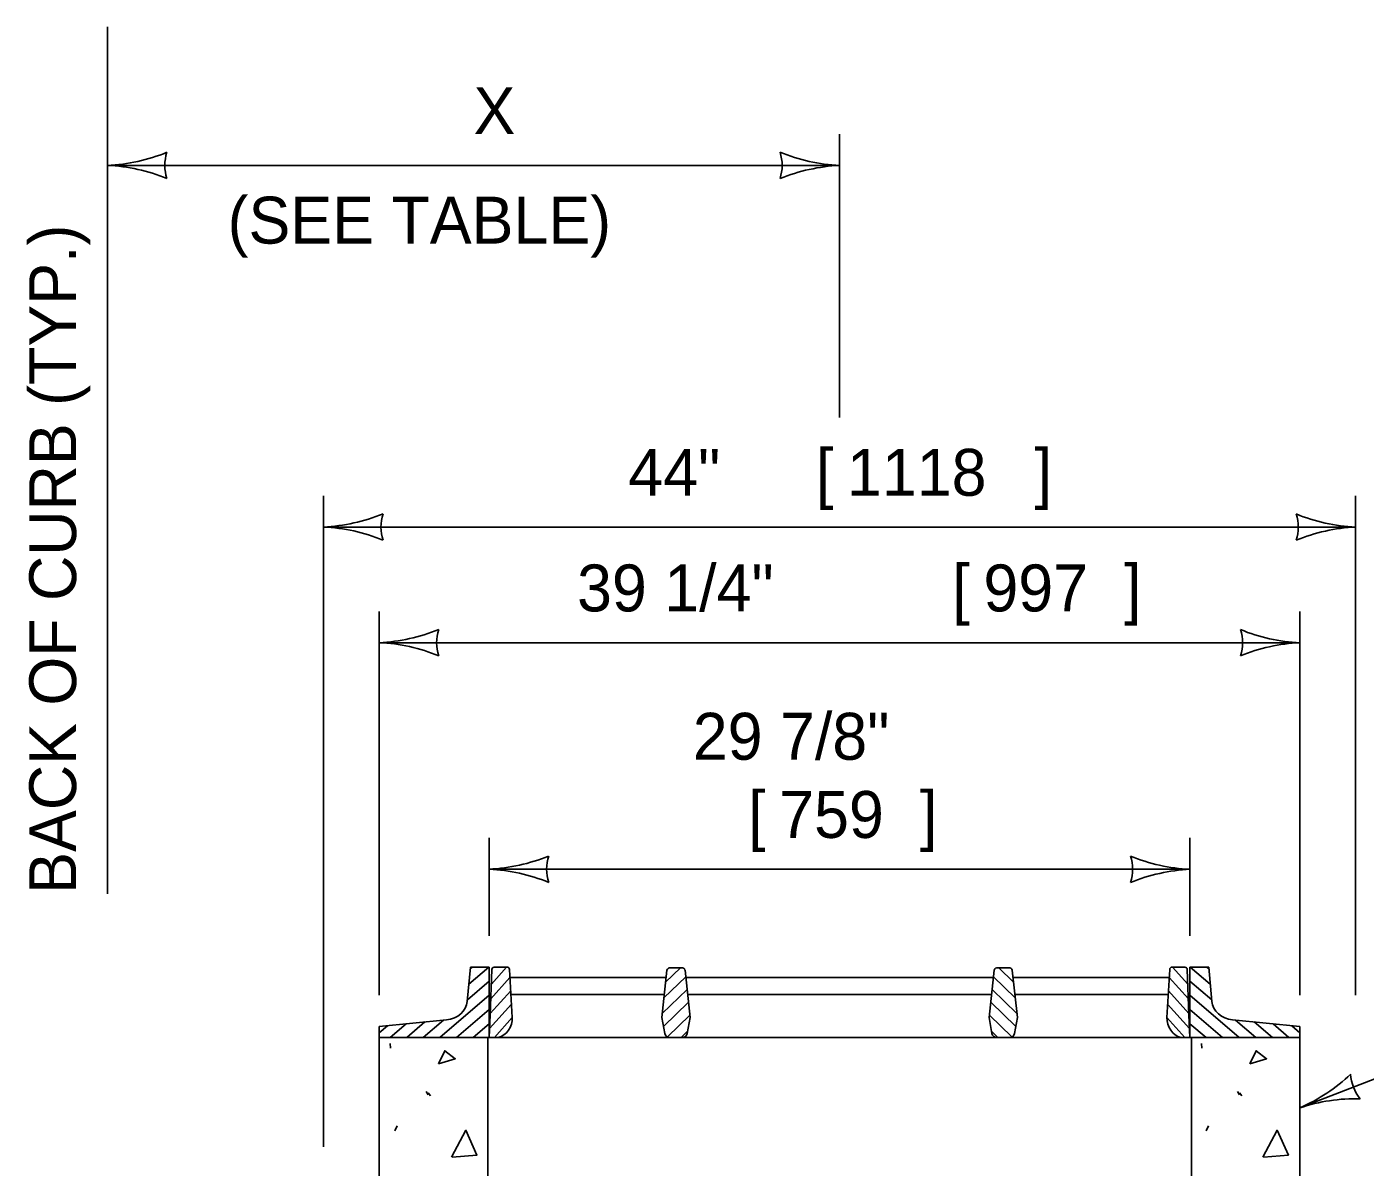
# Model space of a CAD drawing. Extents: x 49991.4 to 50041.6, y 49987.6 to 50011.4.
# Drawn here: x 50037.958 to 50039.67, y 49993.451 to 49994.909 of the extents above; entities that cross this region are included whole.
import ezdxf

# ---------------------------------------------------------------- set-up
doc = ezdxf.new("R2010")
doc.units = 0
for name, color, linetype in [('Level 1', 7, 'Continuous'), ('Level 2', 7, 'Continuous'), ('Level 3', 7, 'Continuous')]:
    doc.layers.add(name, color=color, linetype=linetype)

msp = doc.modelspace()

# ---------------------------------------------------------------- linework, layer by layer
at = {"layer": 'Level 1'}
for p, q in [((50038.5258, 49993.7068), (50038.5217, 49993.6628)), ((50038.5237, 49993.6848), (50038.5493, 49993.7068)), ((50038.5256, 49993.7046), (50038.5281, 49993.7068)), ((50038.5497, 49993.7068), (50038.5258, 49993.7068)), ((50038.5497, 49993.6168), (50038.5497, 49993.7068)), ((50038.5531, 49993.7036), (50038.5511, 49993.6456)), ((50038.5525, 49993.6851), (50038.5719, 49993.7068)), ((50038.5727, 49993.7068), (50038.5561, 49993.7068)), ((50038.5793, 49993.6425), (50038.5757, 49993.7037)), ((50038.777, 49993.703), (50038.7705, 49993.6422)), ((50038.7754, 49993.6875), (50038.7943, 49993.7058)), ((50038.7954, 49993.7058), (50038.7818, 49993.7058)), ((50038.8067, 49993.6422), (50038.8002, 49993.703)), ((50039.189, 49993.6422), (50039.1956, 49993.703)), ((50039.2003, 49993.7058), (50039.2139, 49993.7058)), ((50039.2203, 49993.6875), (50039.2014, 49993.7058)), ((50039.2187, 49993.703), (50039.2252, 49993.6422)), ((50039.4164, 49993.6425), (50039.4201, 49993.7037)), ((50039.4231, 49993.7068), (50039.4396, 49993.7068)), ((50039.4432, 49993.6851), (50039.4238, 49993.7068)), ((50039.4426, 49993.7036), (50039.4446, 49993.6456)), ((50039.446, 49993.6168), (50039.446, 49993.7068)), ((50039.446, 49993.7068), (50039.47, 49993.7068)), ((50039.472, 49993.6848), (50039.4464, 49993.7068)), ((50039.4702, 49993.7046), (50039.4676, 49993.7068)), ((50039.47, 49993.7068), (50039.474, 49993.6628)), ((50038.5219, 49993.6651), (50038.5497, 49993.6889)), ((50038.5518, 49993.6662), (50038.5763, 49993.6934)), ((50038.5763, 49993.6934), (50038.776, 49993.6934)), ((50038.7732, 49993.6674), (50038.8011, 49993.6943)), ((50038.8012, 49993.6934), (50039.1945, 49993.6934)), ((50039.2225, 49993.6674), (50039.1946, 49993.6943)), ((50039.2197, 49993.6934), (50039.4194, 49993.6934)), ((50039.4439, 49993.6662), (50039.4194, 49993.6934)), ((50039.4738, 49993.6651), (50039.446, 49993.6889)), ((50038.4867, 49993.6168), (50038.5497, 49993.6708)), ((50038.5512, 49993.6473), (50038.5773, 49993.6764)), ((50038.5776, 49993.6719), (50038.7737, 49993.6719)), ((50038.771, 49993.6473), (50038.8028, 49993.6781)), ((50038.8035, 49993.6719), (50039.1922, 49993.6719)), ((50039.2247, 49993.6473), (50039.1929, 49993.6781)), ((50039.222, 49993.6719), (50039.4182, 49993.6719)), ((50039.4446, 49993.6473), (50039.4184, 49993.6764)), ((50039.509, 49993.6168), (50039.446, 49993.6708)), ((50038.508, 49993.6168), (50038.5497, 49993.6526)), ((50038.5503, 49993.6281), (50038.5783, 49993.6593)), ((50038.7726, 49993.6308), (50038.8046, 49993.6618)), ((50039.2231, 49993.6308), (50039.1911, 49993.6618)), ((50039.4455, 49993.6281), (50039.4174, 49993.6593)), ((50039.4878, 49993.6168), (50039.446, 49993.6526)), ((50038.4953, 49993.6393), (50038.4091, 49993.6308)), ((50038.4443, 49993.6168), (50038.4674, 49993.6366)), ((50038.4655, 49993.6168), (50038.4914, 49993.6389)), ((50038.5292, 49993.6168), (50038.5497, 49993.6344)), ((50038.5511, 49993.6456), (50038.5497, 49993.6168)), ((50038.5564, 49993.6168), (50038.5793, 49993.6423)), ((50038.7705, 49993.6422), (50038.7742, 49993.622)), ((50038.7777, 49993.6178), (50038.8064, 49993.6455)), ((50038.803, 49993.622), (50038.8067, 49993.6422)), ((50039.1927, 49993.622), (50039.189, 49993.6422)), ((50039.218, 49993.6178), (50039.1894, 49993.6455)), ((50039.2252, 49993.6422), (50039.2215, 49993.622)), ((50039.4393, 49993.6168), (50039.4164, 49993.6423)), ((50039.4446, 49993.6456), (50039.446, 49993.6168)), ((50039.4666, 49993.6168), (50039.446, 49993.6344)), ((50039.5005, 49993.6393), (50039.5866, 49993.6308)), ((50039.5302, 49993.6168), (50039.5043, 49993.6389)), ((50039.5514, 49993.6168), (50039.5283, 49993.6366)), ((50038.4091, 49993.6229), (50038.4195, 49993.6318)), ((50038.4091, 49993.6308), (50038.4091, 49993.6168)), ((50038.4231, 49993.6168), (50038.4434, 49993.6342)), ((50038.7953, 49993.6168), (50038.8035, 49993.6247)), ((50039.2004, 49993.6168), (50039.1922, 49993.6247)), ((50039.5726, 49993.6168), (50039.5523, 49993.6342)), ((50039.5866, 49993.6229), (50039.5763, 49993.6318)), ((50039.5866, 49993.6308), (50039.5866, 49993.6168)), ((50038.4091, 49993.6168), (50038.5497, 49993.6168)), ((50038.4091, 49993.6168), (50039.446, 49993.6168)), ((50038.4229, 49993.6092), (50038.4236, 49993.6031)), ((50038.5497, 49993.6168), (50038.5613, 49993.6168)), ((50038.7807, 49993.6168), (50038.7965, 49993.6168)), ((50039.2151, 49993.6168), (50039.1992, 49993.6168)), ((50039.446, 49993.6168), (50039.4344, 49993.6168)), ((50039.5866, 49993.6168), (50039.446, 49993.6168)), ((50039.4606, 49993.6092), (50039.4613, 49993.6031)), ((50038.4691, 49993.5477), (50038.4718, 49993.5436)), ((50038.4718, 49993.5462), (50038.4745, 49993.5421)), ((50039.5068, 49993.5477), (50039.5095, 49993.5436)), ((50039.5095, 49993.5462), (50039.5122, 49993.5421)), ((50038.4292, 49993.4975), (50038.4319, 49993.5036)), ((50039.4669, 49993.4975), (50039.4696, 49993.5036))]:
    msp.add_line(p, q, dxfattribs=at)
for points in [[(50038.4091, 49993.4368), (50038.4091, 49993.6168), (50038.5479, 49993.6168), (50038.5479, 49993.4368)], [(50039.4479, 49993.4368), (50039.4479, 49993.6168), (50039.5866, 49993.6168), (50039.5866, 49993.4368)]]:
    msp.add_lwpolyline(points, close=True, dxfattribs=at)
for points in [[(50038.4847, 49993.5829), (50038.4928, 49993.5998), (50038.5064, 49993.5896), (50038.4847, 49993.5829)], [(50039.5224, 49993.5829), (50039.5305, 49993.5998), (50039.544, 49993.5896), (50039.5224, 49993.5829)], [(50038.5016, 49993.4637), (50038.5199, 49993.4982), (50038.5341, 49993.4664), (50038.5023, 49993.4637)], [(50039.5393, 49993.4637), (50039.5575, 49993.4982), (50039.5718, 49993.4664), (50039.5399, 49993.4637)]]:
    msp.add_lwpolyline(points, dxfattribs=at)
for centre, major_axis, ratio, start_param, end_param in [((50038.5561, 49993.7034), (0, 0.00334), 0.898406, 0, 1.518438), ((50038.5727, 49993.7034), (0, 0.00334), 0.898406, 4.799667, 6.283204), ((50038.7811, 49993.7019), (0.00417, 0), 0.966535, 1.388426, 2.855422), ((50038.7961, 49993.7019), (-0.00418, 0), 0.966535, 3.427776, 4.894775), ((50039.1996, 49993.7019), (0.00418, 0), 0.966535, 1.38841, 2.855409), ((50039.2147, 49993.7019), (-0.00417, 0), 0.966535, 3.427763, 4.894759), ((50039.4231, 49993.7034), (0, 0.00334), 0.898406, 6.283167, 7.766704), ((50039.4396, 49993.7034), (0, 0.00334), 0.898406, 4.764748, 6.283185), ((50038.4918, 49993.6649), (0.03, 0), 0.857143, 4.827266, 6.204597), ((50039.5039, 49993.6649), (-0.03, 0), 0.857143, 0.078588, 1.45592), ((50038.5562, 49993.6419), (0, 0.0257), 0.898406, 3.361832, 4.736544), ((50039.4395, 49993.6419), (0, 0.0257), 0.898406, 1.546641, 2.921353), ((50038.7807, 49993.6231), (-0.00658, 0), 0.966535, 0.174538, 1.570796), ((50038.7965, 49993.6231), (-0.00658, 0), 0.966535, 1.570796, 2.967065), ((50039.1992, 49993.6231), (-0.00658, 0), 0.966535, 0.174528, 1.570796), ((50039.2151, 49993.6231), (-0.00658, 0), 0.966535, 1.570796, 2.967054)]:
    msp.add_ellipse(centre, major_axis=major_axis, ratio=ratio, start_param=start_param, end_param=end_param, dxfattribs=at)
at = {"layer": 'Level 3'}
for p, q in [((50038.0615, 49994.9094), (50038.0615, 49993.8005)), ((50038.9979, 49994.4096), (50038.9979, 49994.7721)), ((50038.9979, 49994.7321), (50038.0615, 49994.7321)), ((50038.3379, 49993.4768), (50038.3379, 49994.3096)), ((50039.6579, 49993.6708), (50039.6579, 49994.3096)), ((50038.3379, 49994.2696), (50039.6579, 49994.2696)), ((50038.4091, 49993.6708), (50038.4091, 49994.1617)), ((50039.5866, 49993.6708), (50039.5866, 49994.1617)), ((50038.4091, 49994.1217), (50039.5866, 49994.1217)), ((50038.5497, 49993.7468), (50038.5497, 49993.872)), ((50039.446, 49993.7468), (50039.446, 49993.872)), ((50038.5497, 49993.832), (50039.446, 49993.832)), ((50039.5866, 49993.5268), (50040.0652, 49993.7116))]:
    msp.add_line(p, q, dxfattribs=at)
for centre, radius, start, end in [((50038.05, 49994.9648), 0.233, 272.8273, 292.0772), ((50038.1897, 49994.7321), 0.0548, 162.1388, 197.8612), ((50039.007, 49994.9543), 0.2223, 247.456, 267.6395), ((50038.8696, 49994.7321), 0.0548, 342.1388, 17.8612), ((50038.0524, 49994.51), 0.2223, 67.456, 87.6395), ((50039.0094, 49994.4994), 0.233, 92.8273, 112.0772), ((50038.3264, 49994.5023), 0.233, 272.8273, 292.0772), ((50038.3264, 49994.5023), 0.233, 272.8273, 292.0772), ((50038.4661, 49994.2696), 0.0548, 162.1388, 197.8612), ((50038.4661, 49994.2696), 0.0548, 162.1388, 197.8612), ((50039.667, 49994.4917), 0.2223, 247.456, 267.6395), ((50039.5296, 49994.2696), 0.0548, 342.1388, 17.8612), ((50038.3287, 49994.0475), 0.2223, 67.456, 87.6395), ((50038.3287, 49994.0475), 0.2223, 67.456, 87.6395), ((50039.6694, 49994.0369), 0.233, 92.8273, 112.0772), ((50038.3976, 49994.3544), 0.233, 272.8273, 292.0772), ((50038.3976, 49994.3544), 0.233, 272.8273, 292.0772), ((50038.5373, 49994.1217), 0.0548, 162.1388, 197.8612), ((50038.5373, 49994.1217), 0.0548, 162.1388, 197.8612), ((50039.5958, 49994.3438), 0.2223, 247.456, 267.6395), ((50039.4584, 49994.1217), 0.0548, 342.1388, 17.8612), ((50039.5958, 49994.3438), 0.2223, 247.456, 267.6395), ((50039.4584, 49994.1217), 0.0548, 342.1388, 17.8612), ((50038.4, 49993.8996), 0.2223, 67.456, 87.6395), ((50038.4, 49993.8996), 0.2223, 67.456, 87.6395), ((50039.5981, 49993.889), 0.233, 92.8273, 112.0772), ((50039.5981, 49993.889), 0.233, 92.8273, 112.0772), ((50038.5382, 49994.0647), 0.233, 272.8273, 292.0772), ((50038.5382, 49994.0647), 0.233, 272.8273, 292.0772), ((50038.678, 49993.832), 0.0548, 162.1388, 197.8612), ((50038.678, 49993.832), 0.0548, 162.1388, 197.8612), ((50039.4551, 49994.0541), 0.2223, 247.456, 267.6395), ((50039.3178, 49993.832), 0.0548, 342.1388, 17.8612), ((50039.4551, 49994.0541), 0.2223, 247.456, 267.6395), ((50039.3178, 49993.832), 0.0548, 342.1388, 17.8612), ((50038.5406, 49993.6098), 0.2223, 67.456, 87.6395), ((50038.5406, 49993.6098), 0.2223, 67.456, 87.6395), ((50039.4575, 49993.5992), 0.233, 92.8273, 112.0772), ((50039.4575, 49993.5992), 0.233, 92.8273, 112.0772), ((50039.4921, 49993.7397), 0.233, 293.9398, 313.1896), ((50039.4921, 49993.7397), 0.233, 293.9398, 313.1896), ((50039.7062, 49993.5729), 0.0548, 183.2513, 218.9736), ((50039.7062, 49993.5729), 0.0548, 183.2513, 218.9736), ((50039.6581, 49993.3162), 0.2223, 88.5685, 108.752), ((50039.6581, 49993.3162), 0.2223, 88.5685, 108.752)]:
    msp.add_arc(centre, radius, start, end, dxfattribs=at)

# ---------------------------------------------------------------- texts
at = {"layer": 'Level 2'}
for s, rotation, p in [('X', 360, (50038.5297, 49994.7721)), ('(SEE TABLE)', 360, (50038.2152, 49994.6321)), ('BACK OF CURB (TYP.)', 90, (50038.0215, 49993.8005)), ('[', 360, (50038.9676, 49994.3096)), ('1118', 360, (50039.0073, 49994.3096)), (']', 360, (50039.2473, 49994.3096)), ('44" ', 360, (50038.7276, 49994.3096)), ('39 1/4" ', 360, (50038.6621, 49994.1617)), ('[', 360, (50039.1421, 49994.1617)), ('997', 360, (50039.1818, 49994.1617)), (']', 360, (50039.3618, 49994.1617)), ('29 7/8"', 360, (50038.8101, 49993.972)), ('[', 360, (50038.8809, 49993.872)), ('759', 360, (50038.9206, 49993.872)), (']', 360, (50039.1006, 49993.872))]:
    msp.add_text(s, height=0.06, rotation=rotation, dxfattribs=at).set_placement(p)

doc.saveas('drawing.dxf')
